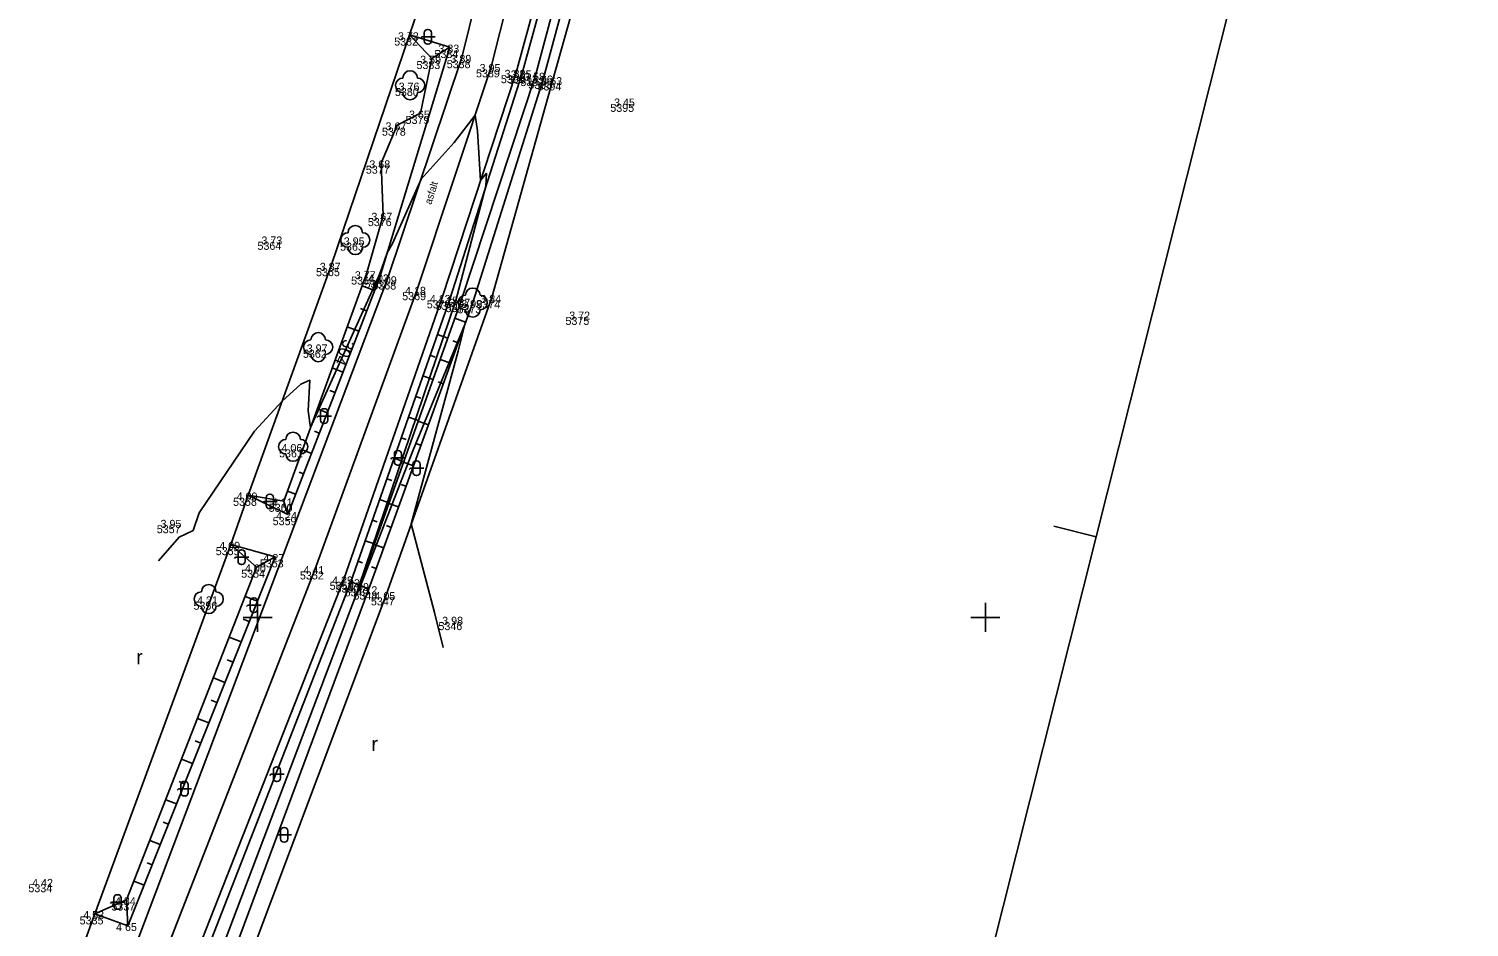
# Model space of a CAD drawing. Extents: x -740053 to -737517, y -1033516 to -1032488.
# Drawn here: x -739015.7 to -738916.8, y -1033271.3 to -1033209.6 of the extents above; entities that cross this region are included whole.
import ezdxf

# ---------------------------------------------------------------- set-up
doc = ezdxf.new("R2010")
doc.units = 0
for name, color, linetype in [('bod-cislo', 7, 'Continuous'), ('bod-oznac', 7, 'Continuous'), ('bod-vyska', 7, 'Continuous'), ('bod-vyska100', 7, 'Continuous'), ('Contours', 7, 'Continuous'), ('Contours text', 7, 'Continuous'), ('ctv-sit', 7, 'Continuous'), ('nazvy-bud-povr', 7, 'Continuous'), ('osa-komunikace', 7, 'Continuous'), ('Predmety bez rozlišeni', 7, 'Continuous'), ('rozhraní kultůr', 7, 'Continuous'), ('silnice', 7, 'Continuous'), ('Technické šrafy', 7, 'Continuous'), ('Terenni-hrana', 7, 'Continuous'), ('Znacky-kultury', 7, 'Continuous')]:
    doc.layers.add(name, color=color, linetype=linetype)

# ---------------------------------------------------------------- blocks, each defined once
blk = doc.blocks.new('POINT_DISPLAY')
blk.add_line((0, 0), (0, 0))
blk = doc.blocks.new('p_strom')
for centre, start, end in [((0, 1), 0, 180), ((-1, 0), 90, 270), ((1, 0), 270, 90), ((0, -1), 180, 0)]:
    blk.add_arc(centre, 1, start, end)
at = {"rotation": -180}
blk.add_blockref('POINT_DISPLAY', (0, 0), dxfattribs=at)
blk = doc.blocks.new('p_orna')
blk.add_text('r', height=2).set_placement((0, 0))
blk = doc.blocks.new('p_neplod')
for p, q in [((-0.82, 0), (-0.99, -0.18)), ((1, 0), (-0.82, 0)), ((-0.49, 0.56), (-0.49, -0.55)), ((0.05, 1.01), (-0.04, 1.01)), ((0.5, -0.55), (0.5, 0.56)), ((-0.04, -1), (0.05, -1))]:
    blk.add_line(p, q)
for centre, start, end in [((-0.04, 0.56), 90, 180), ((0.05, 0.56), 0, 90), ((-0.04, -0.55), 180, 270), ((0.05, -0.55), 270, 0)]:
    blk.add_arc(centre, 0.45, start, end)
blk = doc.blocks.new('ctvsit')
for p, q in [((0, -2), (0, 2)), ((2, 0), (-2, 0))]:
    blk.add_line(p, q)

msp = doc.modelspace()

# ---------------------------------------------------------------- linework, layer by layer
at = {"layer": 'Contours'}
msp.add_lwpolyline([(-738987.247, -1033252.057), (-738987.856, -1033249.654), (-738989.441, -1033243.58), (-738986.212, -1033231.715), (-738985.77, -1033229.883), (-738989.327, -1033238.56), (-738992.942, -1033247.837), (-738993.153, -1033248.292), (-738993.253, -1033248.512), (-738993.015, -1033247.809), (-738992.603, -1033246.59), (-738986.388, -1033228.22), (-738984.31, -1033220.37), (-738984.267, -1033219.484), (-738984.683, -1033219.986), (-738984.896, -1033216.568), (-738985.062, -1033215.488), (-738986.499, -1033217.367), (-738988.77, -1033219.896), (-738990.741, -1033224.298), (-738991.103, -1033224.958), (-738991.458, -1033226.011), (-738991.597, -1033226.378), (-738991.684, -1033226.602), (-738996.359, -1033236.96), (-738996.519, -1033235.814), (-738996.413, -1033233.71), (-738997.04, -1033233.973), (-738998.308, -1033235.145), (-739000.218, -1033237.203), (-739004.009, -1033242.809), (-739004.434, -1033244.019), (-739005.395, -1033244.492), (-739006.817, -1033246.104)], dxfattribs=at)
at = {"layer": 'osa-komunikace'}
for p, q in [((-738983.96, -1033212.16), (-738980.195, -1033197.276)), ((-738989.03, -1033227.47), (-738983.96, -1033212.16)), ((-738996.046, -1033246.658), (-738989.03, -1033227.47)), ((-739006.25, -1033272.85), (-738996.046, -1033246.658))]:
    msp.add_line(p, q, dxfattribs=at)
at = {"layer": 'Predmety bez rozlišeni'}
for p, q in [((-738916.757, -1033142.638), (-738942.39, -1033244.461)), ((-738942.39, -1033244.461), (-738945.299, -1033243.729)), ((-738942.39, -1033244.461), (-738968.023, -1033346.284))]:
    msp.add_line(p, q, dxfattribs=at)
at = {"layer": 'rozhraní kultůr'}
for p, q in [((-738979.71, -1033213.06), (-738975.5, -1033197.9)), ((-738983.91, -1033228.03), (-738979.71, -1033213.06)), ((-738991.17, -1033248.44), (-738983.91, -1033228.03)), ((-739000.99, -1033274.57), (-738991.17, -1033248.44))]:
    msp.add_line(p, q, dxfattribs=at)
at = {"layer": 'silnice'}
for p, q in [((-738985.96, -1033211.53), (-738982.37, -1033196.87)), ((-738982.24, -1033212.56), (-738978.22, -1033197.76)), ((-738991.07, -1033226.74), (-738985.96, -1033211.53)), ((-738987.33, -1033228.03), (-738982.24, -1033212.56)), ((-739008.16, -1033271.96), (-738991.07, -1033226.74)), ((-738994.08, -1033247.37), (-738987.33, -1033228.03)), ((-739004.42, -1033273.67), (-738994.08, -1033247.37))]:
    msp.add_line(p, q, dxfattribs=at)
at = {"layer": 'Technické šrafy'}
for p, q in [((-738991.968, -1033227.545), (-738992.825, -1033227.213)), ((-738992.51, -1033228.943), (-738992.923, -1033228.783)), ((-738993.052, -1033230.342), (-738993.848, -1033230.034)), ((-738985.708, -1033229.713), (-738986.442, -1033229.446)), ((-738987.651, -1033230.571), (-738986.933, -1033230.823)), ((-738986.221, -1033231.123), (-738986.583, -1033230.991)), ((-738993.594, -1033231.741), (-738993.977, -1033231.592)), ((-738988.147, -1033231.987), (-738987.792, -1033232.112)), ((-738994.136, -1033233.139), (-738994.87, -1033232.855)), ((-738986.733, -1033232.533), (-738987.449, -1033232.272)), ((-738988.643, -1033233.403), (-738987.94, -1033233.649)), ((-738987.246, -1033233.942), (-738987.599, -1033233.814)), ((-738994.678, -1033234.538), (-738995.03, -1033234.402)), ((-738989.139, -1033234.819), (-738988.791, -1033234.94)), ((-738995.22, -1033235.937), (-738995.893, -1033235.676)), ((-738989.634, -1033236.234), (-738988.947, -1033236.475)), ((-738988.27, -1033236.762), (-738988.96, -1033236.511)), ((-738995.762, -1033237.335), (-738996.083, -1033237.211)), ((-738990.13, -1033237.65), (-738989.79, -1033237.769)), ((-738996.304, -1033238.734), (-738996.916, -1033238.497)), ((-738988.783, -1033238.172), (-738989.123, -1033238.048)), ((-738990.626, -1033239.066), (-738989.954, -1033239.301)), ((-738989.295, -1033239.581), (-738989.967, -1033239.337)), ((-738996.846, -1033240.133), (-738997.137, -1033240.02)), ((-738991.121, -1033240.481), (-738990.789, -1033240.598)), ((-738989.808, -1033240.991), (-738990.139, -1033240.871)), ((-738997.388, -1033241.531), (-738997.939, -1033241.318)), ((-738991.617, -1033241.897), (-738990.961, -1033242.127)), ((-738990.32, -1033242.401), (-738990.974, -1033242.163)), ((-738992.113, -1033243.313), (-738991.789, -1033243.426)), ((-738990.833, -1033243.811), (-738991.155, -1033243.694)), ((-738992.609, -1033244.729), (-738991.968, -1033244.953)), ((-738991.345, -1033245.22), (-738991.981, -1033244.989)), ((-738993.104, -1033246.144), (-738992.788, -1033246.255)), ((-738991.858, -1033246.63), (-738992.171, -1033246.516)), ((-738993.6, -1033247.56), (-738992.975, -1033247.779)), ((-738992.37, -1033248.04), (-738992.988, -1033247.815)), ((-739000.019, -1033248.887), (-739000.856, -1033248.554)), ((-739000.575, -1033250.281), (-739000.988, -1033250.116)), ((-739001.131, -1033251.674), (-739001.947, -1033251.348)), ((-739001.686, -1033253.067), (-739002.09, -1033252.906)), ((-739002.242, -1033254.461), (-739003.039, -1033254.143)), ((-739002.798, -1033255.854), (-739003.191, -1033255.697)), ((-739003.353, -1033257.247), (-739004.13, -1033256.937)), ((-739003.909, -1033258.64), (-739004.292, -1033258.488)), ((-739004.465, -1033260.034), (-739005.221, -1033259.732)), ((-739005.02, -1033261.427), (-739005.394, -1033261.278)), ((-739005.576, -1033262.82), (-739006.312, -1033262.527)), ((-739006.132, -1033264.214), (-739006.495, -1033264.069)), ((-739006.687, -1033265.607), (-739007.403, -1033265.321)), ((-739007.243, -1033267), (-739007.596, -1033266.859)), ((-739007.799, -1033268.393), (-739008.495, -1033268.116))]:
    msp.add_line(p, q, dxfattribs=at)
at = {"layer": 'Terenni-hrana'}
for p, q in [((-738981.82, -1033212.6), (-738977.76, -1033197.73)), ((-738980.9, -1033212.76), (-738976.92, -1033197.76)), ((-738980.35, -1033212.95), (-738976.29, -1033197.88)), ((-738989.57, -1033209.98), (-738988.67, -1033207.32)), ((-738994.94, -1033225.82), (-738989.57, -1033209.98)), ((-738989.57, -1033209.98), (-738986.79, -1033210.83)), ((-738989.57, -1033209.98), (-738988.04, -1033211.59)), ((-738991.61, -1033226.62), (-738986.79, -1033210.83)), ((-738988.04, -1033211.59), (-738986.79, -1033210.83)), ((-738988.8, -1033215.36), (-738988.04, -1033211.59)), ((-738986.8, -1033228.14), (-738981.82, -1033212.6)), ((-738986.03, -1033228.29), (-738980.9, -1033212.76)), ((-738985.22, -1033228.37), (-738980.35, -1033212.95)), ((-738991.52, -1033218.78), (-738990.41, -1033216.17)), ((-738990.41, -1033216.17), (-738988.8, -1033215.36)), ((-738991.38, -1033222.38), (-738991.52, -1033218.78)), ((-738992.53, -1033226.4), (-738991.38, -1033222.38)), ((-739000.64, -1033241.6), (-738994.94, -1033225.82)), ((-738998.19, -1033242.01), (-738992.53, -1033226.4)), ((-738997.93, -1033242.93), (-738991.61, -1033226.62)), ((-738993.6, -1033247.56), (-738986.8, -1033228.14)), ((-738992.99, -1033247.82), (-738986.03, -1033228.29)), ((-738992.37, -1033248.04), (-738985.22, -1033228.37)), ((-739001.83, -1033244.99), (-739000.64, -1033241.6)), ((-739001.83, -1033244.99), (-739000.64, -1033241.6)), ((-739000.64, -1033241.6), (-738998.19, -1033242.01)), ((-739000.64, -1033241.6), (-738997.93, -1033242.93)), ((-738997.93, -1033242.93), (-738998.19, -1033242.01)), ((-739011.18, -1033270.36), (-739001.83, -1033244.99)), ((-739008.91, -1033271.18), (-738998.8, -1033245.83)), ((-738998.8, -1033245.83), (-739001.83, -1033244.99)), ((-739000.07, -1033246.54), (-739001.83, -1033244.99)), ((-738998.8, -1033245.83), (-739000.07, -1033246.54)), ((-739009, -1033269.41), (-739000.07, -1033246.54)), ((-739003.87, -1033273.88), (-738993.6, -1033247.56)), ((-739002.98, -1033274.13), (-738992.99, -1033247.82)), ((-739002.09, -1033274.25), (-738992.37, -1033248.04)), ((-739011.18, -1033270.36), (-739009, -1033269.41)), ((-739008.91, -1033271.18), (-739009, -1033269.41)), ((-739011.18, -1033270.36), (-739012.37, -1033273.59)), ((-739011.18, -1033270.36), (-739008.91, -1033271.18))]:
    msp.add_line(p, q, dxfattribs=at)

# ---------------------------------------------------------------- block references
at = {"layer": 'bod-oznac'}
for p in [(-738989.57, -1033209.98), (-738986.79, -1033210.83), (-738988.04, -1033211.59), (-738985.96, -1033211.53), (-738983.96, -1033212.16), (-738982.24, -1033212.56), (-738981.82, -1033212.6), (-738980.9, -1033212.76), (-738980.35, -1033212.95), (-738979.71, -1033213.06), (-738989.52, -1033213.44), (-738974.72, -1033214.53), (-738990.41, -1033216.17), (-738988.8, -1033215.36), (-738991.52, -1033218.78), (-738991.38, -1033222.38), (-738998.95, -1033224.01), (-738993.29, -1033224.07), (-738994.94, -1033225.82), (-738992.53, -1033226.4), (-738991.61, -1033226.62), (-738991.07, -1033226.74), (-738989.03, -1033227.47), (-738987.33, -1033228.03), (-738983.91, -1033228.03), (-738986.8, -1033228.14), (-738986.03, -1033228.29), (-738985.22, -1033228.37), (-738977.8, -1033229.17), (-738995.84, -1033231.43), (-738997.56, -1033238.27), (-739000.64, -1033241.6), (-738998.19, -1033242.01), (-739005.88, -1033243.48), (-738997.93, -1033242.93), (-739001.83, -1033244.99), (-738998.8, -1033245.83), (-739000.07, -1033246.54), (-738996.046, -1033246.658), (-738994.08, -1033247.37), (-738993.6, -1033247.56), (-738992.99, -1033247.82), (-739003.36, -1033248.74), (-738992.37, -1033248.04), (-738991.17, -1033248.44), (-738986.53, -1033250.14), (-739014.69, -1033268.15), (-739009, -1033269.41), (-739011.18, -1033270.36), (-739008.91, -1033271.18)]:
    msp.add_blockref('POINT_DISPLAY', p, dxfattribs=at)
at = {"layer": 'ctv-sit', "xscale": 0.5, "yscale": 0.5, "rotation": 180}
for p in [(-739000, -1033250), (-738950, -1033250)]:
    msp.add_blockref('ctvsit', p, dxfattribs=at)
at = {"layer": 'Znacky-kultury', "xscale": 0.5, "yscale": 0.5}
for name, p in [('p_neplod', (-738988.308, -1033210.106)), ('p_strom', (-738989.52, -1033213.44)), ('p_strom', (-738993.29, -1033224.07)), ('p_strom', (-738985.22, -1033228.37)), ('p_strom', (-738995.84, -1033231.43)), ('p_neplod', (-738995.43, -1033236.165)), ('p_strom', (-738997.56, -1033238.27)), ('p_neplod', (-738990.36, -1033239.035)), ('p_neplod', (-738989.082, -1033239.752)), ('p_neplod', (-738999.159, -1033242.041)), ('p_neplod', (-739001.103, -1033245.857)), ('p_strom', (-739003.36, -1033248.74)), ('p_neplod', (-739000.26, -1033249.166)), ('p_orna', (-739008.341, -1033253.224)), ('p_orna', (-738992.183, -1033259.19)), ('p_neplod', (-738998.673, -1033260.778)), ('p_neplod', (-739005.033, -1033261.77)), ('p_neplod', (-738998.174, -1033264.947)), ('p_neplod', (-739009.623, -1033269.556))]:
    msp.add_blockref(name, p, dxfattribs=at)

# ---------------------------------------------------------------- texts
at = {"layer": 'bod-cislo'}
for s, p in [('5382', (-738990.618, -1033210.713)), ('5384', (-738987.851, -1033211.563)), ('5383', (-738989.088, -1033212.323)), ('5388', (-738987.008, -1033212.263)), ('5389', (-738984.995, -1033212.893)), ('5390', (-738983.288, -1033213.293)), ('5391', (-738982.789, -1033213.333)), ('5392', (-738981.948, -1033213.493)), ('5393', (-738981.398, -1033213.683)), ('5380', (-738990.568, -1033214.173)), ('5394', (-738980.771, -1033213.793)), ('5395', (-738975.768, -1033215.263)), ('5379', (-738989.835, -1033216.093)), ('5378', (-738991.458, -1033216.903)), ('5377', (-738992.568, -1033219.513)), ('5376', (-738992.428, -1033223.113)), ('5364', (-739000.011, -1033224.743)), ('5363', (-738994.338, -1033224.803)), ('5365', (-738995.988, -1033226.553)), ('5366', (-738993.578, -1033227.133)), ('5367', (-738992.658, -1033227.353)), ('5368', (-738992.118, -1033227.473)), ('5369', (-738990.065, -1033228.203)), ('5370', (-738988.378, -1033228.763)), ('5371', (-738987.769, -1033228.873)), ('5372', (-738987.078, -1033229.023)), ('5373', (-738986.268, -1033229.103)), ('5374', (-738984.971, -1033228.763)), ('5375', (-738978.848, -1033229.903)), ('5362', (-738996.888, -1033232.163)), ('5361', (-738998.529, -1033239.003)), ('5358', (-739001.688, -1033242.333)), ('5360', (-738999.238, -1033242.743)), ('5357', (-739006.928, -1033244.213)), ('5359', (-738998.965, -1033243.663)), ('5355', (-739002.878, -1033245.723)), ('5354', (-739001.131, -1033247.273)), ('5353', (-738999.848, -1033246.563)), ('5352', (-738997.094, -1033247.391)), ('5351', (-738995.049, -1033248.103)), ('5350', (-738994.648, -1033248.293)), ('5349', (-738994.025, -1033248.553)), ('5348', (-738993.418, -1033248.773)), ('5347', (-738992.218, -1033249.173)), ('5356', (-739004.408, -1033249.473)), ('5346', (-738987.578, -1033250.873)), ('5334', (-739015.751, -1033268.883)), ('5337', (-739010.048, -1033270.143)), ('5335', (-739012.228, -1033271.093))]:
    msp.add_text(s, height=0.55, dxfattribs=at).set_placement(p)
at = {"layer": 'bod-vyska'}
for s, p in [('3 73', (-738990.359, -1033210.347)), ('3 83', (-738987.579, -1033211.197)), ('3 59', (-738988.829, -1033211.957)), ('3 89', (-738986.749, -1033211.897)), ('3 95', (-738984.749, -1033212.527)), ('3 88', (-738983.029, -1033212.927)), ('3 85', (-738982.609, -1033212.967)), ('3 58', (-738981.689, -1033213.127)), ('3 66', (-738981.152, -1033213.317)), ('3 63', (-738980.512, -1033213.427)), ('3 76', (-738990.309, -1033213.807)), ('3 65', (-738989.602, -1033215.727)), ('3 45', (-738975.509, -1033214.897)), ('3 67', (-738991.212, -1033216.537)), ('3 68', (-738992.322, -1033219.147)), ('3 67', (-738992.182, -1033222.747)), ('3 73', (-738999.739, -1033224.377)), ('3 95', (-738994.079, -1033224.437)), ('3 87', (-738995.729, -1033226.187)), ('3 77', (-738993.319, -1033226.767)), ('4 02', (-738992.412, -1033226.987)), ('4 09', (-738991.872, -1033227.107)), ('4 18', (-738989.871, -1033227.837)), ('4 13', (-738988.171, -1033228.397)), ('4 15', (-738987.641, -1033228.507)), ('3 84', (-738984.699, -1033228.397)), ('3 87', (-738986.819, -1033228.657)), ('3 99', (-738986.009, -1033228.737)), ('3 72', (-738978.589, -1033229.537)), ('3 97', (-738996.629, -1033231.797)), ('4 06', (-738998.362, -1033238.637)), ('4 09', (-739001.442, -1033241.967)), ('4 11', (-738999.031, -1033242.377)), ('4 24', (-738998.732, -1033243.297)), ('3 95', (-739006.669, -1033243.847)), ('4 09', (-739002.632, -1033245.357)), ('4 27', (-738999.602, -1033246.197)), ('4 00', (-739000.872, -1033246.907)), ('4 41', (-738996.848, -1033247.025)), ('4 29', (-738994.882, -1033247.737)), ('4 23', (-738994.402, -1033247.927)), ('3 99', (-738993.779, -1033248.187)), ('4 12', (-738993.211, -1033248.407)), ('4 21', (-739004.162, -1033249.107)), ('4 05', (-738991.972, -1033248.807)), ('3 98', (-738987.319, -1033250.507)), ('4 42', (-739015.492, -1033268.517)), ('4 34', (-739009.802, -1033269.777)), ('4 53', (-739011.982, -1033270.727)), ('4 65', (-739009.725, -1033271.547))]:
    msp.add_text(s, height=0.55, dxfattribs=at).set_placement(p)
at = {"layer": 'bod-vyska100'}
for s, p in [('303 73', (-738989.737, -1033210.013)), ('303 83', (-738986.957, -1033210.863)), ('303 59', (-738988.207, -1033211.623)), ('303 89', (-738986.127, -1033211.563)), ('303 95', (-738984.127, -1033212.193)), ('303 88', (-738982.407, -1033212.593)), ('303 85', (-738981.987, -1033212.633)), ('303 58', (-738981.067, -1033212.793)), ('303 66', (-738980.518, -1033212.983)), ('303 63', (-738979.878, -1033213.093)), ('303 76', (-738989.687, -1033213.473)), ('303 45', (-738974.887, -1033214.563)), ('303 67', (-738990.578, -1033216.203)), ('303 65', (-738988.968, -1033215.393)), ('303 68', (-738991.688, -1033218.813)), ('303 67', (-738991.548, -1033222.413)), ('303 73', (-738999.117, -1033224.043)), ('303 95', (-738993.457, -1033224.103)), ('303 87', (-738995.107, -1033225.853)), ('303 77', (-738992.697, -1033226.433)), ('304 02', (-738991.778, -1033226.653)), ('304 09', (-738991.238, -1033226.773)), ('304 18', (-738989.202, -1033227.503)), ('304 13', (-738987.502, -1033228.063)), ('303 84', (-738984.077, -1033228.063)), ('304 15', (-738986.972, -1033228.173)), ('303 87', (-738986.197, -1033228.323)), ('303 99', (-738985.387, -1033228.403)), ('303 72', (-738977.967, -1033229.203)), ('303 97', (-738996.007, -1033231.463)), ('304 06', (-738997.728, -1033238.303)), ('304 09', (-739000.808, -1033241.633)), ('304 11', (-738998.362, -1033242.043)), ('303 95', (-739006.047, -1033243.513)), ('304 24', (-738998.098, -1033242.963)), ('304 09', (-739001.998, -1033245.023)), ('304 27', (-738998.968, -1033245.863)), ('304 00', (-739000.238, -1033246.573)), ('304 41', (-738996.215, -1033246.692)), ('304 29', (-738994.248, -1033247.403)), ('304 23', (-738993.768, -1033247.593)), ('303 99', (-738993.157, -1033247.853)), ('304 21', (-739003.528, -1033248.773)), ('304 12', (-738992.542, -1033248.073)), ('304 05', (-738991.338, -1033248.473)), ('303 98', (-738986.697, -1033250.173)), ('304 42', (-739014.858, -1033268.183)), ('304 34', (-739009.168, -1033269.443)), ('304 53', (-739011.348, -1033270.393)), ('304 65', (-739009.079, -1033271.213))]:
    msp.add_text(s, height=0.05, dxfattribs=at).set_placement(p)
at = {"layer": 'Contours text'}
msp.add_text('304', height=0.8, rotation=245.70588, dxfattribs=at).set_placement((-738994.031, -1033230.831))
at = {"layer": 'nazvy-bud-povr'}
msp.add_text('asfalt', height=0.5, rotation=72.49848, dxfattribs=at).set_placement((-738988.074, -1033221.666))

doc.saveas('drawing.dxf')
